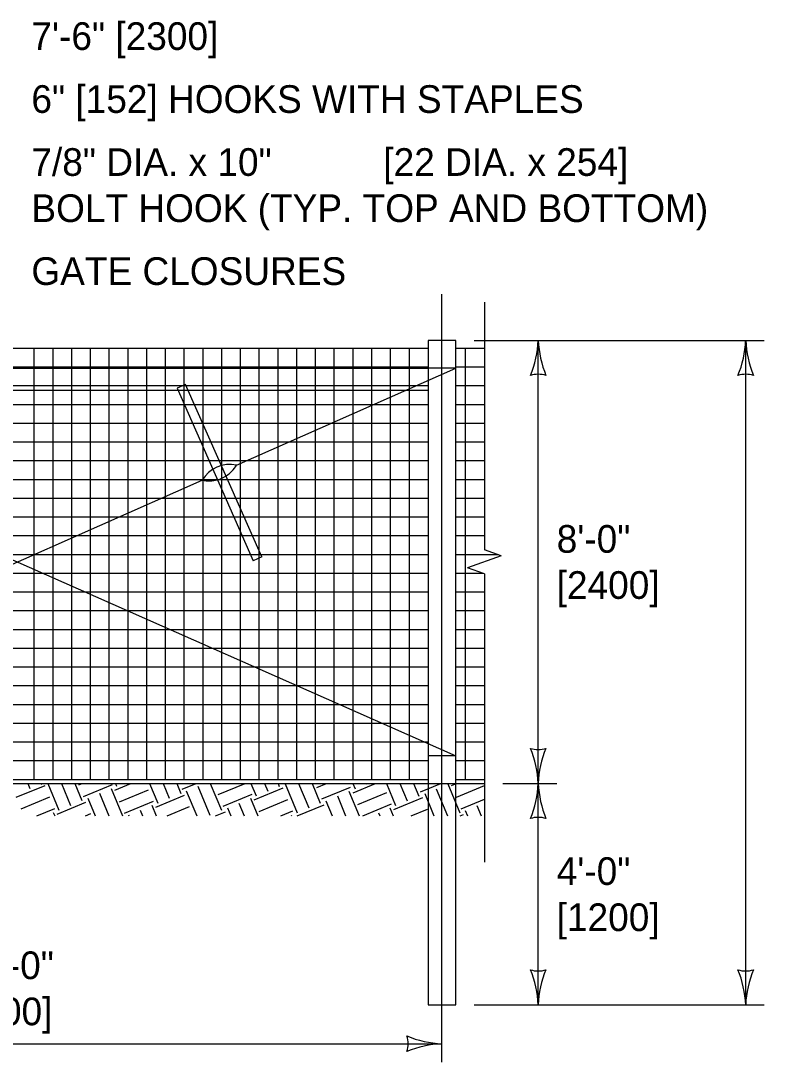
# Model space of a CAD drawing. Extents: x 49991.4 to 50021, y 49987.6 to 50011.4.
# Drawn here: x 50003.939 to 50005.55, y 49989.264 to 49991.521 of the extents above; entities that cross this region are included whole.
import ezdxf

# ---------------------------------------------------------------- set-up
doc = ezdxf.new("R2010")
doc.units = 0
for name, color, linetype in [('Level 1', 7, 'Continuous'), ('Level 2', 7, 'Continuous'), ('Level 3', 7, 'Continuous'), ('Level 4', 7, 'Continuous'), ('Level 5', 7, 'Continuous'), ('Level 6', 7, 'Continuous')]:
    doc.layers.add(name, color=color, linetype=linetype)

msp = doc.modelspace()

# ---------------------------------------------------------------- linework, layer by layer
at = {"layer": 'Level 1'}
for p, q in [((50004.8216, 49990.8281), (50004.8216, 49989.8678)), ((50004.8816, 49990.8281), (50004.8216, 49990.8281)), ((50004.8816, 49989.8678), (50004.8816, 49990.8281)), ((50004.8216, 49990.8107), (50003.0415, 49990.8107)), ((50003.9681, 49989.8759), (50003.9681, 49990.8107)), ((50004.0088, 49989.8759), (50004.0088, 49990.8107)), ((50004.0494, 49989.8759), (50004.0494, 49990.8107)), ((50004.09, 49989.8759), (50004.09, 49990.8107)), ((50004.1307, 49989.8759), (50004.1307, 49990.8107)), ((50004.1713, 49989.8759), (50004.1713, 49990.8107)), ((50004.212, 49989.8759), (50004.212, 49990.8107)), ((50004.2526, 49989.8759), (50004.2526, 49990.8107)), ((50004.2933, 49989.8759), (50004.2933, 49990.8107)), ((50004.3339, 49989.8759), (50004.3339, 49990.8107)), ((50004.3745, 49989.8759), (50004.3745, 49990.8107)), ((50004.4152, 49989.8759), (50004.4152, 49990.8107)), ((50004.4558, 49989.8759), (50004.4558, 49990.8107)), ((50004.4965, 49989.8759), (50004.4965, 49990.8107)), ((50004.5371, 49989.8759), (50004.5371, 49990.8107)), ((50004.5777, 49989.8759), (50004.5777, 49990.8107)), ((50004.6184, 49989.8759), (50004.6184, 49990.8107)), ((50004.659, 49989.8759), (50004.659, 49990.8107)), ((50004.6997, 49989.8759), (50004.6997, 49990.8107)), ((50004.7403, 49989.8759), (50004.7403, 49990.8107)), ((50004.781, 49989.8759), (50004.781, 49990.8107)), ((50004.9435, 49990.8107), (50004.8816, 49990.8107)), ((50004.9029, 49989.8759), (50004.9029, 49990.8107)), ((50002.9815, 49990.768), (50004.8216, 49990.768)), ((50004.8216, 49990.77), (50003.0415, 49990.77)), ((50004.4066, 49990.5579), (50004.8816, 49990.7681)), ((50004.8816, 49990.7681), (50004.8216, 49990.7681)), ((50004.9435, 49990.77), (50004.8816, 49990.77)), ((50004.8216, 49990.7294), (50003.0415, 49990.7294)), ((50003.0415, 49990.7201), (50004.8216, 49990.7201)), ((50004.296, 49990.7324), (50004.2777, 49990.7243)), ((50004.2777, 49990.7243), (50004.4428, 49990.3507)), ((50004.4611, 49990.3588), (50004.296, 49990.7324)), ((50004.9435, 49990.7294), (50004.8816, 49990.7294)), ((50004.8216, 49990.6888), (50003.0415, 49990.6888)), ((50004.9435, 49990.6888), (50004.8816, 49990.6888)), ((50004.8216, 49990.6481), (50003.0415, 49990.6481)), ((50004.9435, 49990.6481), (50004.8816, 49990.6481)), ((50004.8216, 49990.6075), (50003.0415, 49990.6075)), ((50004.9435, 49990.6075), (50004.8816, 49990.6075)), ((50004.8216, 49990.5668), (50003.0415, 49990.5668)), ((50004.9435, 49990.5668), (50004.8816, 49990.5668)), ((50002.9815, 49989.928), (50004.3322, 49990.5251)), ((50004.8216, 49990.5262), (50003.0415, 49990.5262)), ((50003.5309, 49990.5253), (50004.8816, 49989.9281)), ((50004.9435, 49990.5262), (50004.8816, 49990.5262)), ((50004.8216, 49990.4855), (50003.0415, 49990.4855)), ((50004.9435, 49990.4855), (50004.8816, 49990.4855)), ((50004.8216, 49990.4449), (50003.0415, 49990.4449)), ((50004.9435, 49990.4449), (50004.8816, 49990.4449)), ((50004.8216, 49990.4043), (50003.0415, 49990.4043)), ((50004.9435, 49990.4043), (50004.8816, 49990.4043)), ((50004.8216, 49990.3636), (50003.0415, 49990.3636)), ((50004.4611, 49990.3588), (50004.4428, 49990.3507)), ((50004.973, 49990.3636), (50004.8816, 49990.3636)), ((50004.8216, 49990.323), (50003.0415, 49990.323)), ((50004.9414, 49990.323), (50004.8816, 49990.323)), ((50004.8216, 49990.2823), (50003.0415, 49990.2823)), ((50004.9435, 49990.2823), (50004.8816, 49990.2823)), ((50004.8216, 49990.2417), (50003.0415, 49990.2417)), ((50004.9435, 49990.2417), (50004.8816, 49990.2417)), ((50004.8216, 49990.201), (50003.0415, 49990.201)), ((50004.9435, 49990.201), (50004.8816, 49990.201)), ((50004.8216, 49990.1604), (50003.0415, 49990.1604)), ((50004.9435, 49990.1604), (50004.8816, 49990.1604)), ((50004.8216, 49990.1198), (50003.0415, 49990.1198)), ((50004.9435, 49990.1198), (50004.8816, 49990.1198)), ((50004.8216, 49990.0791), (50003.0415, 49990.0791)), ((50004.9435, 49990.0791), (50004.8816, 49990.0791)), ((50004.8216, 49990.0385), (50003.0415, 49990.0385)), ((50004.9435, 49990.0385), (50004.8816, 49990.0385)), ((50004.8216, 49989.9978), (50003.0415, 49989.9978)), ((50004.9435, 49989.9978), (50004.8816, 49989.9978)), ((50004.8216, 49989.9572), (50003.0415, 49989.9572)), ((50004.9435, 49989.9572), (50004.8816, 49989.9572)), ((50004.8816, 49989.9281), (50004.8216, 49989.9281)), ((50004.8216, 49989.9166), (50003.0415, 49989.9166)), ((50004.9435, 49989.9166), (50004.8816, 49989.9166)), ((50000.4081, 49989.8678), (50004.9435, 49989.8678)), ((50004.8216, 49989.8759), (50003.0415, 49989.8759)), ((50003.0415, 49989.8678), (50004.9435, 49989.8678)), ((50003.9292, 49989.8378), (50003.9919, 49989.8638)), ((50003.9541, 49989.8678), (50003.9586, 49989.8568)), ((50003.9834, 49989.8678), (50003.9844, 49989.8653)), ((50003.9975, 49989.8678), (50004.0215, 49989.81)), ((50004.0269, 49989.8678), (50004.0465, 49989.8204)), ((50004.0562, 49989.8678), (50004.0716, 49989.8308)), ((50004.0649, 49989.8647), (50004.0723, 49989.8678)), ((50004.0752, 49989.8396), (50004.1379, 49989.8656)), ((50004.1346, 49989.8569), (50004.1592, 49989.7976)), ((50004.1429, 49989.8535), (50004.1774, 49989.8678)), ((50004.1443, 49989.8678), (50004.1467, 49989.8619)), ((50004.2182, 49989.8678), (50004.2357, 49989.8254)), ((50004.2475, 49989.8678), (50004.2608, 49989.8358)), ((50004.2769, 49989.8678), (50004.2858, 49989.8461)), ((50004.2889, 49989.8552), (50004.3191, 49989.8678)), ((50004.3228, 49989.862), (50004.3487, 49989.7993)), ((50004.3497, 49989.8678), (50004.3738, 49989.8097)), ((50004.367, 49989.8436), (50004.4254, 49989.8678)), ((50004.4377, 49989.8678), (50004.4489, 49989.8408)), ((50004.445, 49989.8324), (50004.5077, 49989.8584)), ((50004.4671, 49989.8678), (50004.474, 49989.8512)), ((50004.4964, 49989.8678), (50004.499, 49989.8616)), ((50004.512, 49989.867), (50004.5379, 49989.8043)), ((50004.541, 49989.8678), (50004.563, 49989.8147)), ((50004.5703, 49989.8678), (50004.588, 49989.8251)), ((50004.5807, 49989.8592), (50004.6012, 49989.8678)), ((50004.591, 49989.8342), (50004.6537, 49989.8601)), ((50004.6584, 49989.8678), (50004.6632, 49989.8562)), ((50004.6589, 49989.8476), (50004.7075, 49989.8678)), ((50004.6877, 49989.8678), (50004.6882, 49989.8666)), ((50004.7312, 49989.8678), (50004.7511, 49989.8198)), ((50004.7606, 49989.8678), (50004.7761, 49989.8302)), ((50004.7899, 49989.8678), (50004.8012, 49989.8405)), ((50004.8049, 49989.8494), (50004.8492, 49989.8678)), ((50004.8643, 49989.8667), (50004.8902, 49989.804)), ((50004.8725, 49989.8632), (50004.8834, 49989.8678)), ((50004.9435, 49989.8759), (50004.8816, 49989.8759)), ((50004.8829, 49989.8382), (50004.9435, 49989.8633)), ((50003.9396, 49989.8128), (50004.0022, 49989.8387)), ((50004.0845, 49989.8361), (50004.1005, 49989.7976)), ((50004.1096, 49989.8465), (50004.1299, 49989.7976)), ((50004.1532, 49989.8284), (50004.2159, 49989.8544)), ((50004.2314, 49989.8168), (50004.294, 49989.8427)), ((50004.2977, 49989.8516), (50004.3201, 49989.7976)), ((50004.3774, 49989.8186), (50004.44, 49989.8445)), ((50004.4368, 49989.8358), (50004.4527, 49989.7976)), ((50004.625, 49989.8409), (50004.6429, 49989.7976)), ((50004.65, 49989.8513), (50004.6722, 49989.7976)), ((50004.6692, 49989.8226), (50004.7319, 49989.8485)), ((50004.7472, 49989.8114), (50004.8099, 49989.8373)), ((50004.8142, 49989.8459), (50004.8342, 49989.7976)), ((50004.8392, 49989.8563), (50004.8635, 49989.7976)), ((50003.9738, 49989.7976), (50004.0126, 49989.8137)), ((50004.0176, 49989.8016), (50004.0802, 49989.8275)), ((50004.1636, 49989.8034), (50004.2262, 49989.8293)), ((50004.2226, 49989.8205), (50004.232, 49989.7976)), ((50004.256, 49989.7976), (50004.3044, 49989.8177)), ((50004.3867, 49989.8151), (50004.394, 49989.7976)), ((50004.4118, 49989.8255), (50004.4233, 49989.7976)), ((50004.4554, 49989.8074), (50004.518, 49989.8333)), ((50004.5382, 49989.7976), (50004.5962, 49989.8217)), ((50004.5999, 49989.8305), (50004.6135, 49989.7976)), ((50004.6799, 49989.7976), (50004.7422, 49989.8235)), ((50004.739, 49989.8148), (50004.7461, 49989.7976)), ((50004.7849, 49989.7976), (50004.8202, 49989.8123)), ((50004.8932, 49989.8131), (50004.9435, 49989.834)), ((50004.9271, 49989.8199), (50004.9364, 49989.7976)), ((50004.0094, 49989.805), (50004.0125, 49989.7976)), ((50004.0789, 49989.7976), (50004.0906, 49989.8025)), ((50004.1725, 49989.7997), (50004.1733, 49989.7976)), ((50004.1975, 49989.8101), (50004.2027, 49989.7976)), ((50004.361, 49989.7976), (50004.3824, 49989.8065)), ((50004.5027, 49989.7976), (50004.5284, 49989.8083)), ((50004.5248, 49989.7994), (50004.5255, 49989.7976)), ((50004.714, 49989.8044), (50004.7168, 49989.7976)), ((50004.8912, 49989.7976), (50004.8984, 49989.8006)), ((50004.9021, 49989.8095), (50004.907, 49989.7976))]:
    msp.add_line(p, q, dxfattribs=at)
for centre, start, end in [((50004.3921, 49990.4901), 77.9863, 149.7127), ((50004.3467, 49990.5929), 302.1462, 329.7127), ((50004.3467, 49990.5929), 257.9863, 285.5694)]:
    msp.add_arc(centre, 0.0694, start, end, dxfattribs=at)
at = {"layer": 'Level 3'}
for p, q in [((50004.9216, 49990.8281), (50005.5498, 49990.8281)), ((50005.0602, 49989.8678), (50005.0602, 49990.8281)), ((50005.5098, 49989.388), (50005.5098, 49990.8281)), ((50004.9835, 49989.8679), (50005.1002, 49989.8679)), ((50005.0602, 49989.388), (50005.0602, 49989.8678)), ((50004.9216, 49989.3881), (50005.5498, 49989.3881)), ((50003.0115, 49989.3038), (50004.8516, 49989.3038))]:
    msp.add_line(p, q, dxfattribs=at)
for centre, radius, start, end in [((50004.8381, 49990.8372), 0.2223, 337.456, 357.6395), ((50005.2929, 49990.8396), 0.233, 182.8273, 202.0772), ((50005.2876, 49990.8372), 0.2223, 337.456, 357.6395), ((50005.7425, 49990.8396), 0.233, 182.8273, 202.0772), ((50005.0602, 49990.6999), 0.0548, 72.1388, 107.8612), ((50005.5098, 49990.6999), 0.0548, 72.1388, 107.8612), ((50005.0602, 49989.996), 0.0548, 252.1388, 287.8612), ((50004.8275, 49989.8563), 0.233, 2.8273, 22.0772), ((50005.2823, 49989.8586), 0.2223, 157.456, 177.6395), ((50004.8381, 49989.877), 0.2223, 337.456, 357.6395), ((50005.2929, 49989.8793), 0.233, 182.8273, 202.0772), ((50005.0602, 49989.7396), 0.0548, 72.1388, 107.8612), ((50005.0602, 49989.5162), 0.0548, 252.1388, 287.8612), ((50004.8275, 49989.3765), 0.233, 2.8273, 22.0772), ((50005.2823, 49989.3789), 0.2223, 157.456, 177.6395), ((50005.5098, 49989.5162), 0.0548, 252.1388, 287.8612), ((50005.2771, 49989.3765), 0.233, 2.8273, 22.0772), ((50005.7319, 49989.3789), 0.2223, 157.456, 177.6395), ((50004.8607, 49989.5259), 0.2223, 247.456, 267.6395), ((50004.7234, 49989.3038), 0.0548, 342.1388, 17.8612), ((50004.8631, 49989.0711), 0.233, 92.8273, 112.0772)]:
    msp.add_arc(centre, radius, start, end, dxfattribs=at)
at = {"layer": 'Level 4'}
for p, q in [((50004.8216, 49989.8678), (50004.8216, 49989.388)), ((50004.8816, 49989.388), (50004.8816, 49989.8678)), ((50004.8216, 49989.388), (50004.8816, 49989.388))]:
    msp.add_line(p, q, dxfattribs=at)
msp.add_arc((50004.3467, 49990.5929), 0.0694, 285.5694, 302.1462, dxfattribs=at)
at = {"layer": 'Level 5'}
msp.add_line((50004.8516, 49989.2638), (50004.8516, 49990.9281), dxfattribs=at)
at = {"layer": 'Level 6'}
for p, q in [((50004.9435, 49990.9107), (50004.9435, 49990.3741)), ((50004.9801, 49990.3611), (50004.907, 49990.3352)), ((50004.9801, 49990.3611), (50004.9435, 49990.3741)), ((50004.9435, 49990.3222), (50004.907, 49990.3352)), ((50004.9435, 49990.3222), (50004.9435, 49989.6976))]:
    msp.add_line(p, q, dxfattribs=at)

# ---------------------------------------------------------------- texts
at = {"layer": 'Level 2'}
for s, height, p in [('7\'-6" [2300]', 0.060003, (50003.9619, 49991.4576)), ('6" [152] HOOKS WITH STAPLES', 0.060003, (50003.9619, 49991.3212)), ('7/8" DIA. x 10"  ', 0.060003, (50003.9619, 49991.1847)), ('[22 DIA. x 254] ', 0.060003, (50004.7246, 49991.1847)), ('BOLT HOOK (TYP. TOP AND BOTTOM)', 0.060003, (50003.9619, 49991.0847)), ('GATE CLOSURES', 0.06, (50003.9619, 49990.9483)), ('8\'-0"', 0.06, (50005.1002, 49990.3679)), ('[2400]', 0.06, (50005.1002, 49990.2679)), ('4\'-0"', 0.06, (50005.1002, 49989.6479)), ('[1200]', 0.06, (50005.1002, 49989.5479)), ('15\'-0"', 0.06, (50003.8063, 49989.4438)), ('[4600]', 0.06, (50003.7845, 49989.3438))]:
    msp.add_text(s, height=height, dxfattribs=at).set_placement(p)

doc.saveas('drawing.dxf')
